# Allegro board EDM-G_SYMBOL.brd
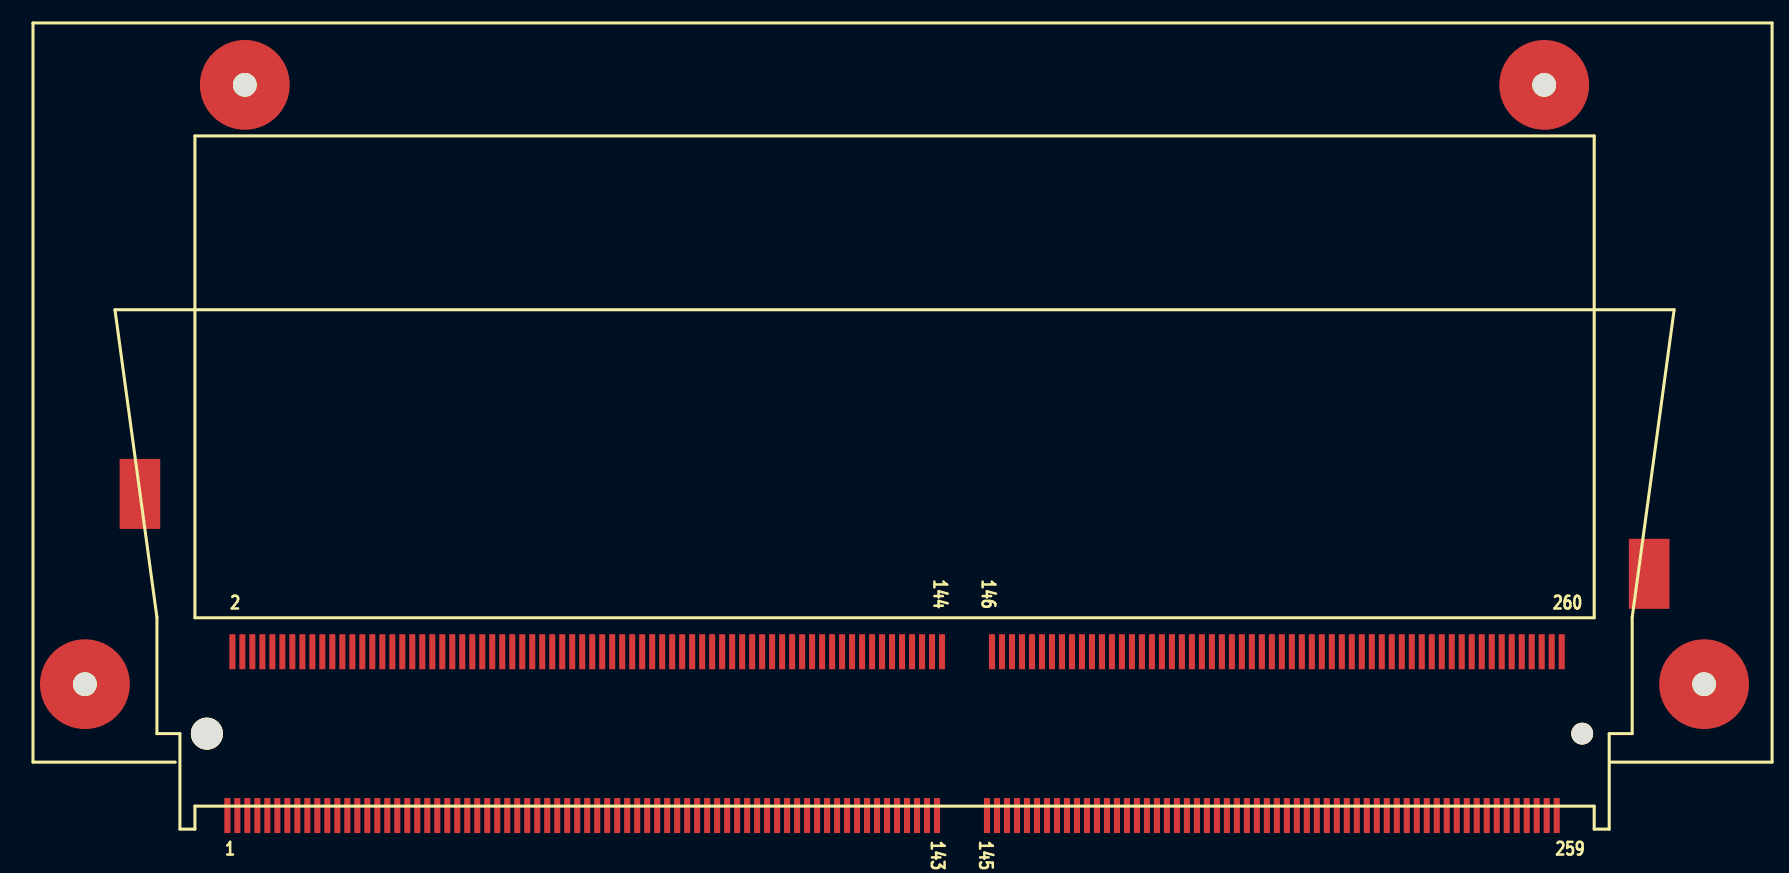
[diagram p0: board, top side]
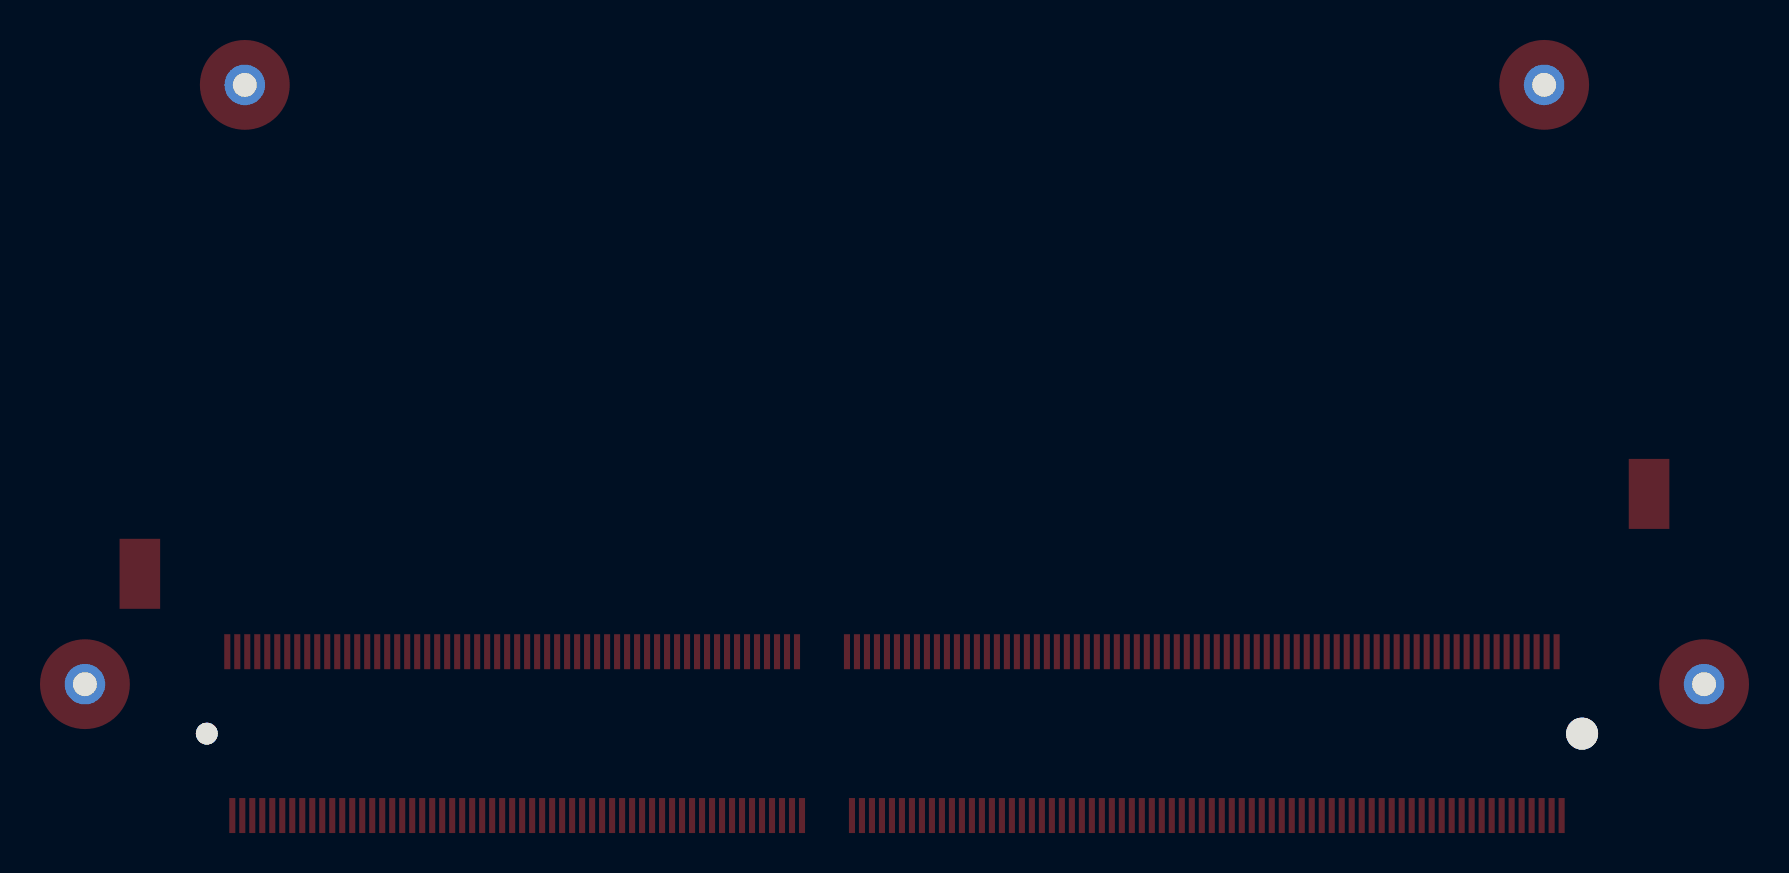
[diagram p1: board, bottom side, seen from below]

No outline. copper layers: TOP, BOTTOM. Coordinates in mm from the lowest, leftmost part position.

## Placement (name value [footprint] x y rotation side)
HOLE8  MCT177B80D47-X  [MCT177B80D47]  0 2.48 0 top
HOLE9  MCT177B80D47-X  [MCT177B80D47]  8 32.48 0 top
HOLE21  MCT177B80D47-X  [MCT177B80D47]  81 2.48 0 top
HOLE22  MCT177B80D47-X  [MCT177B80D47]  73 32.47 0 top
J1  SODIMM_260_CONNECTOR/GF  [SODDR4_ASAA826-EASB0-XH]  40.5 0 180 top

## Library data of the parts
HOLE8 HOLE9 HOLE21 HOLE22 = MCT177B80D47: room: 1
J1 = SODDR4_ASAA826-EASB0-XH: room: 2

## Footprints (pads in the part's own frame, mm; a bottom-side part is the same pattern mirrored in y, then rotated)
MCT177B80D47
  round 4.496 hole 1.194: 1(0,0)
SODDR4_ASAA826-EASB0-XH
  round 1.092 hole 1.092 unplated: (-34.4,0)
  round 1.6 hole 1.6 unplated: (34.4,0)
  rect 0.305x1.753 smd: 1(33.375,4.1) 2(33.125,-4.1) 3(32.875,4.1) 4(32.625,-4.1) 5(32.375,4.1) 6(32.125,-4.1) 7(31.875,4.1) 8(31.625,-4.1) 9(31.375,4.1) 10(31.125,-4.1) 11(30.875,4.1) 12(30.625,-4.1) 13(30.375,4.1) 14(30.125,-4.1) 15(29.875,4.1) 16(29.625,-4.1) 17(29.375,4.1) 18(29.125,-4.1) 19(28.875,4.1) 20(28.625,-4.1) 21(28.375,4.1) 22(28.125,-4.1) 23(27.875,4.1) 24(27.625,-4.1) 25(27.375,4.1) 26(27.125,-4.1) 27(26.875,4.1) 28(26.625,-4.1) 29(26.375,4.1) 30(26.125,-4.1) 31(25.875,4.1) 32(25.625,-4.1) 33(25.375,4.1) 34(25.125,-4.1) 35(24.875,4.1) 36(24.625,-4.1) 37(24.375,4.1) 38(24.125,-4.1) 39(23.875,4.1) 40(23.625,-4.1) 41(23.375,4.1) 42(23.125,-4.1) 43(22.875,4.1) 44(22.625,-4.1) 45(22.375,4.1) 46(22.125,-4.1) 47(21.875,4.1) 48(21.625,-4.1) 49(21.375,4.1) 50(21.125,-4.1) 51(20.875,4.1) 52(20.625,-4.1) 53(20.375,4.1) 54(20.125,-4.1) 55(19.875,4.1) 56(19.625,-4.1) 57(19.375,4.1) 58(19.125,-4.1) 59(18.875,4.1) 60(18.625,-4.1) 61(18.375,4.1) 62(18.125,-4.1) 63(17.875,4.1) 64(17.625,-4.1) 65(17.375,4.1) 66(17.125,-4.1) 67(16.875,4.1) 68(16.625,-4.1) 69(16.375,4.1) 70(16.125,-4.1) 71(15.875,4.1) 72(15.625,-4.1) 73(15.375,4.1) 74(15.125,-4.1) 75(14.875,4.1) 76(14.625,-4.1) 77(14.375,4.1) 78(14.125,-4.1) 79(13.875,4.1) 80(13.625,-4.1) 81(13.375,4.1) 82(13.125,-4.1) 83(12.875,4.1) 84(12.625,-4.1) 85(12.375,4.1) 86(12.125,-4.1) 87(11.875,4.1) 88(11.625,-4.1) 89(11.375,4.1) 90(11.125,-4.1) 91(10.875,4.1) 92(10.625,-4.1) 93(10.375,4.1) 94(10.125,-4.1) 95(9.875,4.1) 96(9.625,-4.1) 97(9.375,4.1) 98(9.125,-4.1) 99(8.875,4.1) 100(8.625,-4.1) 101(8.375,4.1) 102(8.125,-4.1) 103(7.875,4.1) 104(7.625,-4.1) 105(7.375,4.1) 106(7.125,-4.1) 107(6.875,4.1) 108(6.625,-4.1) 109(6.375,4.1) 110(6.125,-4.1) 111(5.875,4.1) 112(5.625,-4.1) 113(5.375,4.1) 114(5.125,-4.1) 115(4.875,4.1) 116(4.625,-4.1) 117(4.375,4.1) 118(4.125,-4.1) 119(3.875,4.1) 120(3.625,-4.1) 121(3.375,4.1) 122(3.125,-4.1) 123(2.875,4.1) 124(2.625,-4.1) 125(2.375,4.1) 126(2.125,-4.1) 127(1.875,4.1) 128(1.625,-4.1) 129(1.375,4.1) 130(1.125,-4.1) 131(0.875,4.1) 132(0.625,-4.1) 133(0.375,4.1) 134(0.125,-4.1) 135(-0.125,4.1) 136(-0.375,-4.1) 137(-0.625,4.1) 138(-0.875,-4.1) 139(-1.125,4.1) 140(-1.375,-4.1) 141(-1.625,4.1) 142(-1.875,-4.1) 143(-2.125,4.1) 144(-2.375,-4.1) 145(-4.625,4.1) 146(-4.875,-4.1) 147(-5.125,4.1) 148(-5.375,-4.1) 149(-5.625,4.1) 150(-5.875,-4.1) 151(-6.125,4.1) 152(-6.375,-4.1) 153(-6.625,4.1) 154(-6.875,-4.1) 155(-7.125,4.1) 156(-7.375,-4.1) 157(-7.625,4.1) 158(-7.875,-4.1) 159(-8.125,4.1) 160(-8.375,-4.1) 161(-8.625,4.1) 162(-8.875,-4.1) 163(-9.125,4.1) 164(-9.375,-4.1) 165(-9.625,4.1) 166(-9.875,-4.1) 167(-10.125,4.1) 168(-10.375,-4.1) 169(-10.625,4.1) 170(-10.875,-4.1) 171(-11.125,4.1) 172(-11.375,-4.1) 173(-11.625,4.1) 174(-11.875,-4.1) 175(-12.125,4.1) 176(-12.375,-4.1) 177(-12.625,4.1) 178(-12.875,-4.1) 179(-13.125,4.1) 180(-13.375,-4.1) 181(-13.625,4.1) 182(-13.875,-4.1) 183(-14.125,4.1) 184(-14.375,-4.1) 185(-14.625,4.1) 186(-14.875,-4.1) 187(-15.125,4.1) 188(-15.375,-4.1) 189(-15.625,4.1) 190(-15.875,-4.1) 191(-16.125,4.1) 192(-16.375,-4.1) 193(-16.625,4.1) 194(-16.875,-4.1) 195(-17.125,4.1) 196(-17.375,-4.1) 197(-17.625,4.1) 198(-17.875,-4.1) 199(-18.125,4.1) 200(-18.375,-4.1) 201(-18.625,4.1) 202(-18.875,-4.1) 203(-19.125,4.1) 204(-19.375,-4.1) 205(-19.625,4.1) 206(-19.875,-4.1) 207(-20.125,4.1) 208(-20.375,-4.1) 209(-20.625,4.1) 210(-20.875,-4.1) 211(-21.125,4.1) 212(-21.375,-4.1) 213(-21.625,4.1) 214(-21.875,-4.1) 215(-22.125,4.1) 216(-22.375,-4.1) 217(-22.625,4.1) 218(-22.875,-4.1) 219(-23.125,4.1) 220(-23.375,-4.1) 221(-23.625,4.1) 222(-23.875,-4.1) 223(-24.125,4.1) 224(-24.375,-4.1) 225(-24.625,4.1) 226(-24.875,-4.1) 227(-25.125,4.1) 228(-25.375,-4.1) 229(-25.625,4.1) 230(-25.875,-4.1) 231(-26.125,4.1) 232(-26.375,-4.1) 233(-26.625,4.1) 234(-26.875,-4.1) 235(-27.125,4.1) 236(-27.375,-4.1) 237(-27.625,4.1) 238(-27.875,-4.1) 239(-28.125,4.1) 240(-28.375,-4.1) 241(-28.625,4.1) 242(-28.875,-4.1) 243(-29.125,4.1) 244(-29.375,-4.1) 245(-29.625,4.1) 246(-29.875,-4.1) 247(-30.125,4.1) 248(-30.375,-4.1) 249(-30.625,4.1) 250(-30.875,-4.1) 251(-31.125,4.1) 252(-31.375,-4.1) 253(-31.625,4.1) 254(-31.875,-4.1) 255(-32.125,4.1) 256(-32.375,-4.1) 257(-32.625,4.1) 258(-32.875,-4.1) 259(-33.125,4.1) 260(-33.375,-4.1)
  rect 2.032x3.505 smd: P1(-37.75,-8) P2(37.75,-12)

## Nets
GND: HOLE8.1 HOLE9.1 HOLE21.1 HOLE22.1

Pads without a net: J1 1 2 3 4 5 6 7 8 9 10 11 12 13 14 15 16 17 18 19 20 21 22 23 24 25 26 27 28 29 30 31 32 33 34 35 36 37 38 39 40 41 42 43 44 45 46 47 48 49 50 51 52 53 54 55 56 57 58 59 60 61 62 63 64 65 66 67 68 69 70 71 72 73 74 75 76 77 78 79 80 81 82 83 84 85 86 87 88 89 90 91 92 93 94 95 96 97 98 99 100 101 102 103 104 105 106 107 108 109 110 111 112 113 114 115 116 117 118 119 120 121 122 123 124 125 126 127 128 129 130 131 132 133 134 135 136 137 138 139 140 141 142 143 144 145 146 147 148 149 150 151 152 153 154 155 156 157 158 159 160 161 162 163 164 165 166 167 168 169 170 171 172 173 174 175 176 177 178 179 180 181 182 183 184 185 186 187 188 189 190 191 192 193 194 195 196 197 198 199 200 201 202 203 204 205 206 207 208 209 210 211 212 213 214 215 216 217 218 219 220 221 222 223 224 225 226 227 228 229 230 231 232 233 234 235 236 237 238 239 240 241 242 243 244 245 246 247 248 249 250 251 252 253 254 255 256 257 258 259 260 P1 P2

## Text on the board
COMPVAL_TYPE_TOP: {\Fgdt;n}\Ftxt;6 | {\Fgdt;n}\Ftxt;3.2 HOLE | 1.6 | 80 | 125
DISPLAY_TOP: {\Fgdt;n}\Ftxt;6 | {\Fgdt;n}\Ftxt;3.2 HOLE | 1.6 | 80 | 125
User.6: {\Fgdt;n}\Ftxt;3.2 HOLE | 1.6 | 85 | 125 | {\Fgdt;n}\Ftxt;6
User.10: {\Fgdt;n}\Ftxt;3.2 HOLE | 1.6 | 85 | 125 | {\Fgdt;n}\Ftxt;6
User.11: {\Fgdt;n}\Ftxt;4.2 | {\Fgdt;n}\Ftxt;6.5
User.20: FIGURE | SIZE | 8.0 | 10.0 | 12.0 | 14.0 | 16.0 | 20.0 | 28.0 | 32.0 | 35.0 | 36.0 | 40.0 | 41.0 | 47.0 | 60.0 | 63.0 | 83.0 | 91.0 | 165.0 | 26.0 | 30.0 | 43.0 | 118.0 | 126.0 | 128.0 | 30.0x18.0 | 43.0x20.0 | 47.0x24.0 | 60.0x20.0 | 83.0x35.0 | 106.0x35.0 | 118.0x32.0 | 37.0x26.0 | DRILL CHART: TOP to BOTTOM | ALL UNITS ARE IN MILS | PLATED | NON-PLATED | QTY | 63 | 1319 | 60 | 42 | 12 | 4 | 50 | 10 | 6 | 2 | 1
